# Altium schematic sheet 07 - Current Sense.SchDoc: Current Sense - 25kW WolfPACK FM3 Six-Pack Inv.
size 431 x 279 mm; Date: 07/2023; DocumentNumber: CRD25DA12N-FMC; Revision: 1.1; SheetNumber: 7; SheetTotal: 8; SheetSize: B
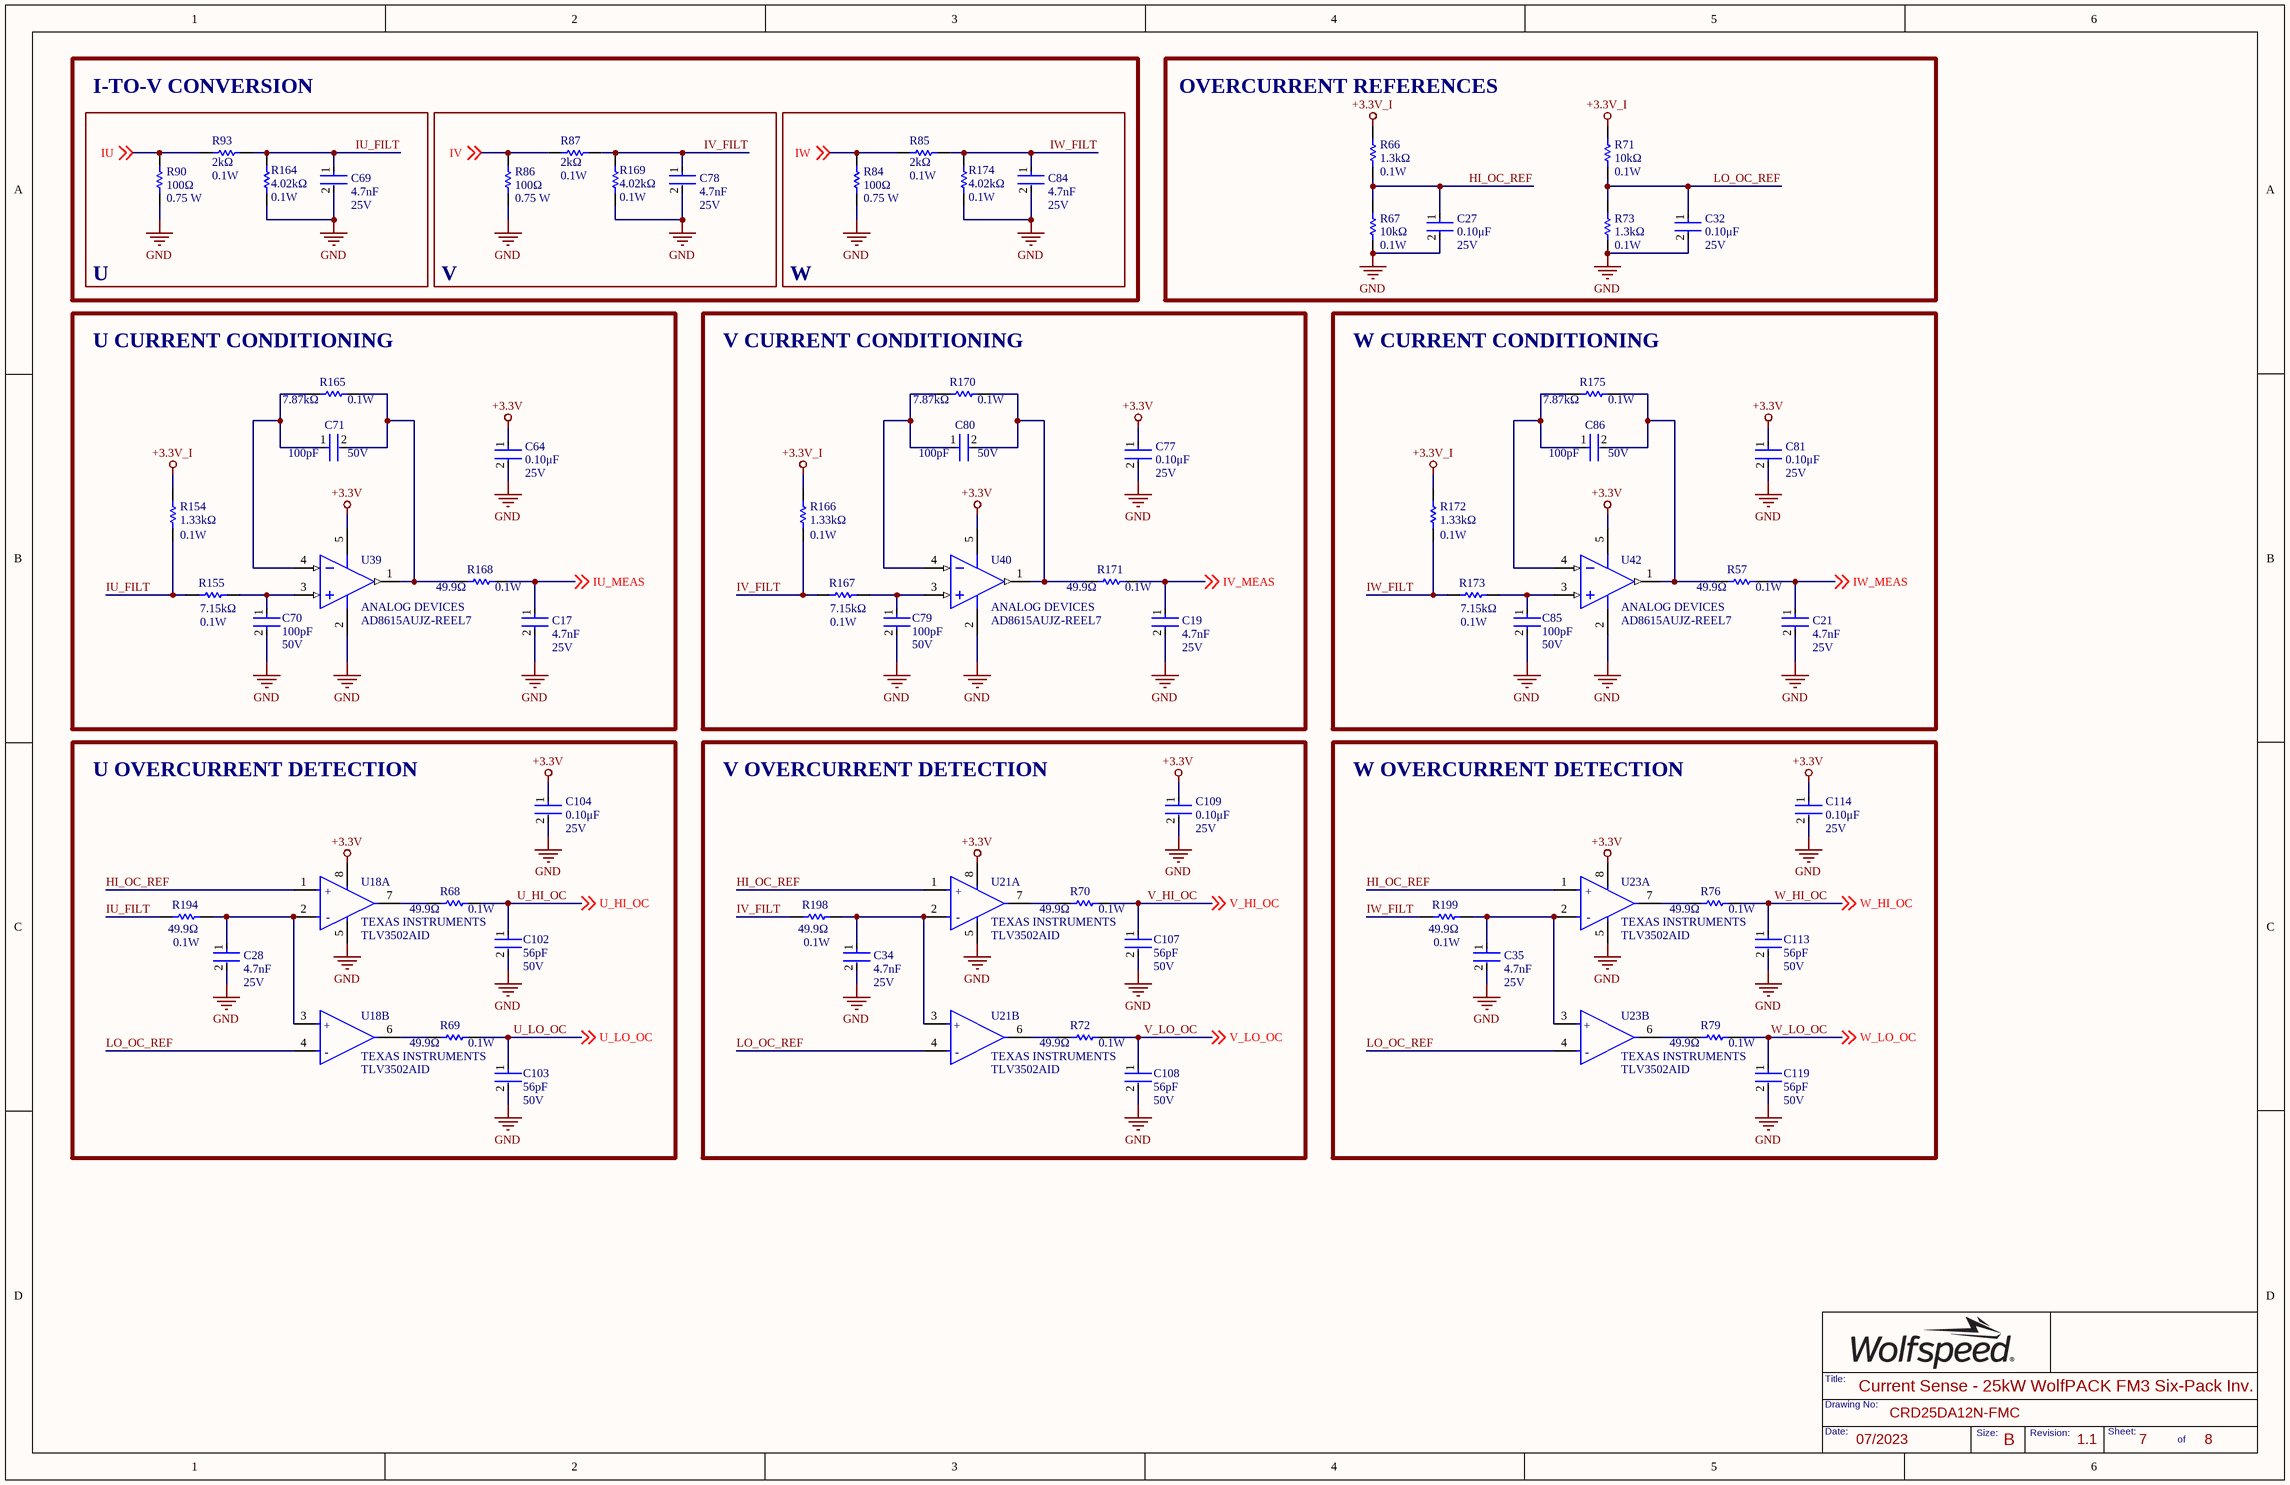
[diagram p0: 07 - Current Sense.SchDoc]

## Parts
C17  Voltage Rating: 25V  Capacitance: 4.7nF  [FP-C0603C-CF-IPC_B]  (hidden comment: C0603C472K3RAC7867)
C19  Voltage Rating: 25V  Capacitance: 4.7nF  [FP-C0603C-CF-IPC_B]  (hidden comment: C0603C472K3RAC7867)
C21  Voltage Rating: 25V  Capacitance: 4.7nF  [FP-C0603C-CF-IPC_B]  (hidden comment: C0603C472K3RAC7867)
C27  Voltage Rating: 25V  Capacitance: 0.10μF  [FP-C0603C-CF-IPC_B]  (hidden comment: C0603C104K3RACTU)
C28  Voltage Rating: 25V  Capacitance: 4.7nF  [FP-C0603C-CF-IPC_B]  (hidden comment: C0603C472K3RAC7867)
C32  Voltage Rating: 25V  Capacitance: 0.10μF  [FP-C0603C-CF-IPC_B]  (hidden comment: C0603C104K3RACTU)
C34  Voltage Rating: 25V  Capacitance: 4.7nF  [FP-C0603C-CF-IPC_B]  (hidden comment: C0603C472K3RAC7867)
C35  Voltage Rating: 25V  Capacitance: 4.7nF  [FP-C0603C-CF-IPC_B]  (hidden comment: C0603C472K3RAC7867)
C64  Voltage Rating: 25V  Capacitance: 0.10μF  [FP-C0603C-CF-IPC_B]  (hidden comment: C0603C104K3RACTU)
C69  Voltage Rating: 25V  Capacitance: 4.7nF  [FP-C0603C-CF-IPC_B]  (hidden comment: C0603C472K3RAC7867)
C70  Capacitance: 100pF  Voltage: 50V  [FP-C0603C-CF-IPC_B]  (hidden comment: CL10C101JB8NNNC)
C71  Capacitance: 100pF  Voltage: 50V  [FP-C0603C-CF-IPC_B]  (hidden comment: CL10C101JB8NNNC)
C77  Voltage Rating: 25V  Capacitance: 0.10μF  [FP-C0603C-CF-IPC_B]  (hidden comment: C0603C104K3RACTU)
C78  Voltage Rating: 25V  Capacitance: 4.7nF  [FP-C0603C-CF-IPC_B]  (hidden comment: C0603C472K3RAC7867)
C79  Capacitance: 100pF  Voltage: 50V  [FP-C0603C-CF-IPC_B]  (hidden comment: CL10C101JB8NNNC)
C80  Capacitance: 100pF  Voltage: 50V  [FP-C0603C-CF-IPC_B]  (hidden comment: CL10C101JB8NNNC)
C81  Voltage Rating: 25V  Capacitance: 0.10μF  [FP-C0603C-CF-IPC_B]  (hidden comment: C0603C104K3RACTU)
C84  Voltage Rating: 25V  Capacitance: 4.7nF  [FP-C0603C-CF-IPC_B]  (hidden comment: C0603C472K3RAC7867)
C85  Capacitance: 100pF  Voltage: 50V  [FP-C0603C-CF-IPC_B]  (hidden comment: CL10C101JB8NNNC)
C86  Capacitance: 100pF  Voltage: 50V  [FP-C0603C-CF-IPC_B]  (hidden comment: CL10C101JB8NNNC)
C102  Capacitance: 56pF  Voltage Rating: 50V  [FP-C0603C-CF-IPC_B]  (hidden comment: CL10C560JB8NNNC)
C103  Capacitance: 56pF  Voltage Rating: 50V  [FP-C0603C-CF-IPC_B]  (hidden comment: CL10C560JB8NNNC)
C104  Voltage Rating: 25V  Capacitance: 0.10μF  [FP-C0603C-CF-IPC_B]  (hidden comment: C0603C104K3RACTU)
C107  Capacitance: 56pF  Voltage Rating: 50V  [FP-C0603C-CF-IPC_B]  (hidden comment: CL10C560JB8NNNC)
C108  Capacitance: 56pF  Voltage Rating: 50V  [FP-C0603C-CF-IPC_B]  (hidden comment: CL10C560JB8NNNC)
C109  Voltage Rating: 25V  Capacitance: 0.10μF  [FP-C0603C-CF-IPC_B]  (hidden comment: C0603C104K3RACTU)
C113  Capacitance: 56pF  Voltage Rating: 50V  [FP-C0603C-CF-IPC_B]  (hidden comment: CL10C560JB8NNNC)
C114  Voltage Rating: 25V  Capacitance: 0.10μF  [FP-C0603C-CF-IPC_B]  (hidden comment: C0603C104K3RACTU)
C119  Capacitance: 56pF  Voltage Rating: 50V  [FP-C0603C-CF-IPC_B]  (hidden comment: CL10C560JB8NNNC)
R57  Resistance: 49.9Ω  Power Rating: 0.1W  [FP-MCR03-IPC_B]  (hidden comment: ERJ-3EKF49R9V)
R66  Power Rating: 0.1W  Resistance: 1.3kΩ  [FP-MCR03-IPC_B]  (hidden comment: ERA3AEB132V)
R67  Resistance: 10kΩ  Max Power Dissipation: 0.1W  [FP-MCR03-IPC_B]  (hidden comment: ERJ3EKF1002V)
R68  Resistance: 49.9Ω  Power Rating: 0.1W  [FP-MCR03-IPC_B]  (hidden comment: ERJ-3EKF49R9V)
R69  Resistance: 49.9Ω  Power Rating: 0.1W  [FP-MCR03-IPC_B]  (hidden comment: ERJ-3EKF49R9V)
R70  Resistance: 49.9Ω  Power Rating: 0.1W  [FP-MCR03-IPC_B]  (hidden comment: ERJ-3EKF49R9V)
R71  Resistance: 10kΩ  Max Power Dissipation: 0.1W  [FP-MCR03-IPC_B]  (hidden comment: ERJ3EKF1002V)
R72  Resistance: 49.9Ω  Power Rating: 0.1W  [FP-MCR03-IPC_B]  (hidden comment: ERJ-3EKF49R9V)
R73  Power Rating: 0.1W  Resistance: 1.3kΩ  [FP-MCR03-IPC_B]  (hidden comment: ERA3AEB132V)
R76  Resistance: 49.9Ω  Power Rating: 0.1W  [FP-MCR03-IPC_B]  (hidden comment: ERJ-3EKF49R9V)
R79  Resistance: 49.9Ω  Power Rating: 0.1W  [FP-MCR03-IPC_B]  (hidden comment: ERJ-3EKF49R9V)
R84  value 100Ω  Power: 0.75 W  [RESC2010(5025)_N]  (hidden comment: RC2010FK-07100RL)
R85  Resistance: 2kΩ  Power Rating: 0.1W  [FP-MCR03-IPC_B]  (hidden comment: RT0603DRE072KL)
R86  value 100Ω  Power: 0.75 W  [RESC2010(5025)_N]  (hidden comment: RC2010FK-07100RL)
R87  Resistance: 2kΩ  Power Rating: 0.1W  [FP-MCR03-IPC_B]  (hidden comment: RT0603DRE072KL)
R90  value 100Ω  Power: 0.75 W  [RESC2010(5025)_N]  (hidden comment: RC2010FK-07100RL)
R93  Resistance: 2kΩ  Power Rating: 0.1W  [FP-MCR03-IPC_B]  (hidden comment: RT0603DRE072KL)
R154  Power Rating: 0.1W  Resistance: 1.33kΩ  [FP-MCR03-IPC_B]  (hidden comment: RMCF0603FT1K33)
R155  Resistance: 7.15kΩ  Power Rating: 0.1W  [FP-MCR03-IPC_B]  (hidden comment: RMCF0603FT7K15)
R164  Resistance: 4.02kΩ  Power Rating: 0.1W  [FP-MCR03-IPC_B]  (hidden comment: ERA3AEB4021V)
R165  Resistance: 7.87kΩ  Max Power Dissipation: 0.1W  [FP-MCR03-IPC_B]  (hidden comment: RC0603FR-077K87L)
R166  Power Rating: 0.1W  Resistance: 1.33kΩ  [FP-MCR03-IPC_B]  (hidden comment: RMCF0603FT1K33)
R167  Resistance: 7.15kΩ  Power Rating: 0.1W  [FP-MCR03-IPC_B]  (hidden comment: RMCF0603FT7K15)
R168  Resistance: 49.9Ω  Power Rating: 0.1W  [FP-MCR03-IPC_B]  (hidden comment: ERJ-3EKF49R9V)
R169  Resistance: 4.02kΩ  Power Rating: 0.1W  [FP-MCR03-IPC_B]  (hidden comment: ERA3AEB4021V)
R170  Resistance: 7.87kΩ  Max Power Dissipation: 0.1W  [FP-MCR03-IPC_B]  (hidden comment: RC0603FR-077K87L)
R171  Resistance: 49.9Ω  Power Rating: 0.1W  [FP-MCR03-IPC_B]  (hidden comment: ERJ-3EKF49R9V)
R172  Power Rating: 0.1W  Resistance: 1.33kΩ  [FP-MCR03-IPC_B]  (hidden comment: RMCF0603FT1K33)
R173  Resistance: 7.15kΩ  Power Rating: 0.1W  [FP-MCR03-IPC_B]  (hidden comment: RMCF0603FT7K15)
R174  Resistance: 4.02kΩ  Power Rating: 0.1W  [FP-MCR03-IPC_B]  (hidden comment: ERA3AEB4021V)
R175  Resistance: 7.87kΩ  Max Power Dissipation: 0.1W  [FP-MCR03-IPC_B]  (hidden comment: RC0603FR-077K87L)
R194  Resistance: 49.9Ω  Power Rating: 0.1W  [FP-MCR03-IPC_B]  (hidden comment: ERJ-3EKF49R9V)
R198  Resistance: 49.9Ω  Power Rating: 0.1W  [FP-MCR03-IPC_B]  (hidden comment: ERJ-3EKF49R9V)
R199  Resistance: 49.9Ω  Power Rating: 0.1W  [FP-MCR03-IPC_B]  (hidden comment: ERJ-3EKF49R9V)
U18  TLV3502AID  Manufacturer Print: TEXAS INSTRUMENTS  [FP-D0008A-IPC_B]  (parts A,B of 2)
U21  TLV3502AID  Manufacturer Print: TEXAS INSTRUMENTS  [FP-D0008A-IPC_B]  (parts A,B of 2)
U23  TLV3502AID  Manufacturer Print: TEXAS INSTRUMENTS  [FP-D0008A-IPC_B]  (parts A,B of 2)
U39  Manufacturer: ANALOG DEVICES  [ADI-UJ-5_M]  (hidden comment: AD8615AUJZ-REEL7)
U40  Manufacturer: ANALOG DEVICES  [ADI-UJ-5_M]  (hidden comment: AD8615AUJZ-REEL7)
U42  Manufacturer: ANALOG DEVICES  [ADI-UJ-5_M]  (hidden comment: AD8615AUJZ-REEL7)

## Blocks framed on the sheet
V: C78 R86 R87 R169
W: C84 R84 R85 R174
OVERCURRENT REFERENCES: C27 C32 R66 R67 R71 R73
U CURRENT CONDITIONING: C17 C64 C70 C71 R154 R155 R165 R168 U39
V CURRENT CONDITIONING: C19 C77 C79 C80 R166 R167 R170 R171 U40
W CURRENT CONDITIONING: C21 C81 C85 C86 R57 R172 R173 R175 U42
U OVERCURRENT DETECTION: C28 C102-C104 R68 R69 R194 U18
V OVERCURRENT DETECTION: C34 C107-C109 R70 R72 R198 U21
W OVERCURRENT DETECTION: C35 C113 C114 C119 R76 R79 R199 U23

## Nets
+3.3V: C64.1 C77.1 C81.1 C104.1 C109.1 C114.1 U18.8(V+) U21.8(V+) U23.8(V+) U39.5(+V) U40.5(+V) U42.5(+V)
+3.3V_I: R66.2 R71.2 R154.2 R166.2 R172.2
GND: C17.2 C19.2 C21.2 C27.2 C28.2 C32.2 C34.2 C35.2 C64.2 C69.2 C70.2 C77.2 C78.2 C79.2 C81.2 C84.2 C85.2 C102.2 C103.2 C104.2 C107.2 C108.2 C109.2 C113.2 C114.2 C119.2 R67.1 R73.1 R84.1 R86.1 R90.1 R164.1 R169.1 R174.1 U18.5(V-) U21.5(V-) U23.5(V-) U39.2(-V) U40.2(-V) U42.2(-V)
HI_OC_REF: C27.1 R66.1 R67.2 U18.1(+IN_A) U21.1(+IN_A) U23.1(+IN_A)
IU: R90.2 R93.1 ; off-sheet IU
IU_FILT: C69.1 R93.2 R154.1 R155.1 R164.2 R194.1
IU_MEAS: C17.1 R168.2 ; off-sheet IU_MEAS
IV: R86.2 R87.1 ; off-sheet IV
IV_FILT: C78.1 R87.2 R166.1 R167.1 R169.2 R198.1
IV_MEAS: C19.1 R171.2 ; off-sheet IV_MEAS
IW: R84.2 R85.1 ; off-sheet IW
IW_FILT: C84.1 R85.2 R172.1 R173.1 R174.2 R199.1
IW_MEAS: C21.1 R57.2 ; off-sheet IW_MEAS
LO_OC_REF: C32.1 R71.1 R73.2 U18.4(-IN_B) U21.4(-IN_B) U23.4(-IN_B)
U_HI_OC: C102.1 R68.2 ; off-sheet U_HI_OC
U_LO_OC: C103.1 R69.2 ; off-sheet U_LO_OC
V_HI_OC: C107.1 R70.2 ; off-sheet V_HI_OC
V_LO_OC: C108.1 R72.2 ; off-sheet V_LO_OC
W_HI_OC: C113.1 R76.2 ; off-sheet W_HI_OC
W_LO_OC: C119.1 R79.2 ; off-sheet W_LO_OC
NetC28_1: C28.1 R194.2 U18.2(-IN_A) U18.3(+IN_B)
NetC34_1: C34.1 R198.2 U21.2(-IN_A) U21.3(+IN_B)
NetC35_1: C35.1 R199.2 U23.2(-IN_A) U23.3(+IN_B)
NetC70_1: C70.1 R155.2 U39.3(+IN)
NetC71_1: C71.1 R165.1 U39.4(-IN)
NetC71_2: C71.2 R165.2 R168.1 U39.1(OUT)
NetC79_1: C79.1 R167.2 U40.3(+IN)
NetC80_1: C80.1 R170.1 U40.4(-IN)
NetC80_2: C80.2 R170.2 R171.1 U40.1(OUT)
NetC85_1: C85.1 R173.2 U42.3(+IN)
NetC86_1: C86.1 R175.1 U42.4(-IN)
NetC86_2: C86.2 R57.1 R175.2 U42.1(OUT)
NetR68_1: R68.1 U18.7(OUT_A)
NetR69_1: R69.1 U18.6(OUT_B)
NetR70_1: R70.1 U21.7(OUT_A)
NetR72_1: R72.1 U21.6(OUT_B)
NetR76_1: R76.1 U23.7(OUT_A)
NetR79_1: R79.1 U23.6(OUT_B)

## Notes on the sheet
- I-TO-V CONVERSION
- U

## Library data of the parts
C17 C19 C21 C28 C34 C35 C69 C78 C84 = C0603C472K3RAC7867: CAP CER 4700PF 25V 10% X7R 0603; Manufacturer: KEMET; Manufacturer Part Number: C0603C472K3RACTU; Dielectric Material: Ceramic; Value: 4.7nF
C27 C32 C64 C77 C81 C104 C109 C114 = CMP-2006-03057-2: CAP CER 0.1UF 25V X7R 0603; Manufacturer: KEMET; Value: 0.10μF; Material: Ceramic; Tolerance: 0.1; Temperature Coefficient: 30ppm/°C; Automotive Grade: Grade 1
C70 C71 C79 C80 C85 C86 = CL10C101JB8NNNC: CAP CER 100PF 50V C0G/NP0 0603; Manufacturer: SAMSUNG; Material: Ceramic; Tolerance: 5%; Dielectric: C0G; Temperature Coefficient: 300ppm/°C
C102 C103 C107 C108 C113 C119 = CL10C560JB8NNNC: CAP CER 56PF 50V C0G/NP0 0603; Manufacturer: SAMSUNG; Material: Ceramic; Tolerance: 5%; Dielectric: C0G; Temperature Coefficient: 30ppm/°C
R57 R68-R70 R72 R76 R79 R168 R171 R194 R198 R199 = ERJ-3EKF49R9V: RES SMD 49.9 OHM 1% 1/10W 0603; Manufacturer: PANASONIC; Temperature Coefficient: 100ppm/°C; Voltage Rating: 75V; Max Power Dissipation: 100mW; Voltage Rating (DC): 50V; Working Voltage: 6V; Value: 49.9Ω
R66 R73 = ERA3AEB132V: RES SMD 1.3K OHM 0.1% 1/10W 0603; Manufacturer: PANASONIC; Manufacturer Part Number: ERA-3AEB132V; Temperature Coefficient: 25ppm/°C; Voltage Rating: 75V; Max Power Dissipation: 100mW; Value: 1.3kΩ
R67 R71 = ERJ3EKF1002V: RES SMD 10K OHM 1% 1/10W 0603; Manufacturer: PANASONIC; Manufacturer Part Number: ERJ-3EKF1002V; Temperature Coefficient: 100ppm/°C; Power Rating: 100mW; Voltage Rating: 75V; Value: 10kΩ
R84 R86 R90 = CMP-1017-00397-1: RES 100 OHM 1% 3/4W 2010; Manufacturer: YAGEO; Case-Metric: 5025
R85 R87 R93 = RT0603DRE072KL: RES SMD 2K OHM 0.5% 1/10W 0603; Manufacturer: YAGEO; Temperature Coefficient: 50ppm/°C; Voltage Rating: 75V; Max Power Dissipation: 100mW; Voltage Rating (DC): 50V; Value: 2kΩ
R154 R166 R172 = RMCF0603FT1K33: RES 1.33K OHM 1% 1/10W 0603; Manufacturer: STACKPOLE; Max Power Dissipation: 100mW; Temperature Coefficient: 100ppm/°C; Value: 1.33kΩ
R155 R167 R173 = RMCF0603FT7K15: RES 7.15K OHM 1% 1/10W 0603; Manufacturer: STACKPOLE; Max Power Dissipation: 100mW; Temperature Coefficient: 100ppm/°C; Value: 7.15kΩ
R164 R169 R174 = ERA3AEB4021V: RES SMD 4.02KOHM 0.1% 1/10W 0603; Manufacturer: PANASONIC; Manufacturer Part Number: ERA-3AEB4021V; Voltage Rating: 75V; Temperature Coefficient: 25ppm/°C; Max Power Dissipation: 100mW; Value: 4.02kΩ
R165 R170 R175 = RC0603FR-077K87L: RES 7.87K OHM 1% 1/10W 0603; Manufacturer: YAGEO; Power Rating: 100mW; Temperature Coefficient: 100ppm/°C; Voltage Rating: 50V; Value: 7.87kΩ
U18 U21 U23 = CMP-04896-000023-1: IC COMPARATOR R-R HI-SPD 8-SOIC; Nominal Supply Current: 3.2mA; Standoff Height: 0.11mm; Max Supply Voltage: 5.5V; Min Supply Voltage: 2.2V; Input Bias Current: 0.000002uA; Number Of Channels: 2; Max Junction Temp: +150°C; Input Offset Voltage: 1mV
U39 U40 U42 = CMP-0384-02059-2: IC OPAMP GP 1 CIRCUIT TSOT23-5; Generic Part Number: AD8615; Iq/Amp: 1.7mA; V Span Max: 6V; Amplifiers Per Package: 1; Small Signal Bandwidth: 23MHz; Input Offset Voltage: 80uV; V Span Min: 2.7V; Slew Rate: 12V/us; Input Bias Current: 200fA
